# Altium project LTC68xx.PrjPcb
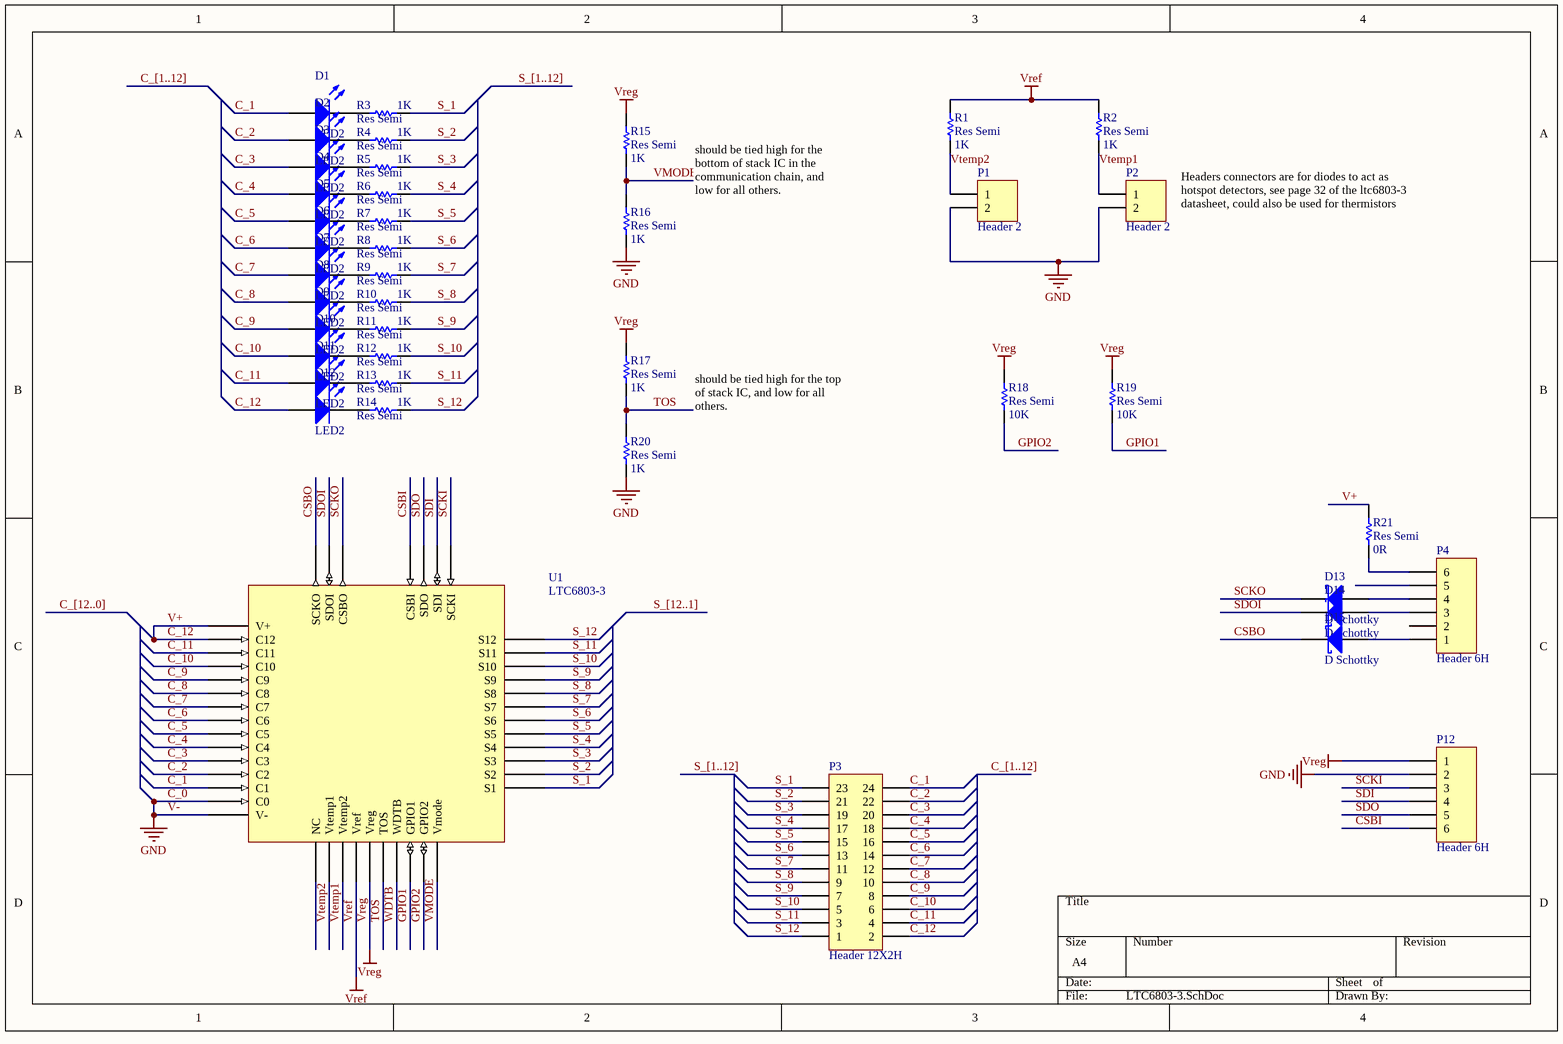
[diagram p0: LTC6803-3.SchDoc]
1 sheet, 42 parts. Net scope: global (net labels, ports and power ports of the same name join across sheets).
Board file: LTC68xx.PcbDoc

## Sheet LTC6803-3.SchDoc
size A4

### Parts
D1  LED2  [6-0805_N]
D2  LED2  [6-0805_N]
D3  LED2  [6-0805_N]
D4  LED2  [6-0805_N]
D5  LED2  [6-0805_N]
D6  LED2  [6-0805_N]
D7  LED2  [6-0805_N]
D8  LED2  [6-0805_N]
D9  LED2  [6-0805_N]
D10  LED2  [6-0805_N]
D11  LED2  [6-0805_N]
D12  LED2  [6-0805_N]
D13  D Schottky  [SMB]
D14  D Schottky  [SMB]
D15  D Schottky  [SMB]
P1  Header 2  [HDR1X2]
P2  Header 2  [HDR1X2]
P3  Header 12X2H  [HDR2X12H]
P4  Header 6H  [HDR1X6H]
P12  Header 6H  [HDR1X6H]
R1  Res Semi  value 1K  [6-0805_L]
R2  Res Semi  value 1K  [6-0805_L]
R3  Res Semi  value 1K  [6-0805_L]
R4  Res Semi  value 1K  [6-0805_L]
R5  Res Semi  value 1K  [6-0805_L]
R6  Res Semi  value 1K  [6-0805_L]
R7  Res Semi  value 1K  [6-0805_L]
R8  Res Semi  value 1K  [6-0805_L]
R9  Res Semi  value 1K  [6-0805_L]
R10  Res Semi  value 1K  [6-0805_L]
R11  Res Semi  value 1K  [6-0805_L]
R12  Res Semi  value 1K  [6-0805_L]
R13  Res Semi  value 1K  [6-0805_L]
R14  Res Semi  value 1K  [6-0805_L]
R15  Res Semi  value 1K  [6-0805_L]
R16  Res Semi  value 1K  [6-0805_L]
R17  Res Semi  value 1K  [6-0805_L]
R18  Res Semi  value 10K  [6-0805_L]
R19  Res Semi  value 10K  [6-0805_L]
R20  Res Semi  value 1K  [6-0805_L]
R21  Res Semi  value 0R  [6-0805_L]
U1  LTC6803-3  [SOP44]

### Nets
C_0: P1.2 P2.2 P12.2 R16.1 R20.1 U1.29(C0) U1.30(V-)  [also labelled GND, V-]
Vref: R1.2 R2.2 U1.34(Vref)
Vreg: P12.1 R15.2 R17.2 R18.2 R19.2 U1.35(Vreg)
C_1: D1.1(A) P3.24 U1.27(C1)
C_2: D2.1(A) P3.22 U1.25(C2)
C_3: D3.1(A) P3.20 U1.23(C3)
C_4: D4.1(A) P3.18 U1.21(C4)
C_5: D5.1(A) P3.16 U1.19(C5)
C_6: D6.1(A) P3.14 U1.17(C6)
C_7: D7.1(A) P3.12 U1.15(C7)
C_8: D8.1(A) P3.10 U1.13(C8)
C_9: D9.1(A) P3.8 U1.11(C9)
C_10: D10.1(A) P3.6 U1.9(C10)
C_11: D11.1(A) P3.4 U1.7(C11)
C_12: D12.1(A) P3.2 R21.2 U1.4(V+) U1.5(C12)  [also labelled V+]
CSBI: P12.6 U1.44(CSBI)
CSBO: D15.2(K) U1.3(SCKO)
GPIO1: R19.1 U1.38(GPIO1)
GPIO2: R18.1 U1.39(GPIO2)
S_1: P3.23 R3.2 U1.28(S1)
S_2: P3.21 R4.2 U1.26(S2)
S_3: P3.19 R5.2 U1.24(S3)
S_4: P3.17 R6.2 U1.22(S4)
S_5: P3.15 R7.2 U1.20(S5)
S_6: P3.13 R8.2 U1.18(S6)
S_7: P3.11 R9.2 U1.16(S7)
S_8: P3.9 R10.2 U1.14(S8)
S_9: P3.7 R11.2 U1.12(S9)
S_10: P3.5 R12.2 U1.10(S10)
S_11: P3.3 R13.2 U1.8(S11)
S_12: P3.1 R14.2 U1.6(S12)
SCKI: P12.3 U1.41(SCKI)
SCKO: D13.2(K) U1.1(CSBO)
SDI: P12.4 U1.42(SDI)
SDO: P12.5 U1.43(SDO)
SDOI: D14.2(K) U1.2(SDOI)
TOS: R17.1 R20.2 U1.36(TOS)
VMODE: R15.1 R16.2 U1.40(Vmode)
Vtemp1: P2.1 R2.1 U1.33(Vtemp2)
Vtemp2: P1.1 R1.1 U1.32(Vtemp1)
WDTB: U1.37(WDTB)
NetD1_2: D1.2(K) R3.1
NetD2_2: D2.2(K) R4.1
NetD3_2: D3.2(K) R5.1
NetD4_2: D4.2(K) R6.1
NetD5_2: D5.2(K) R7.1
NetD6_2: D6.2(K) R8.1
NetD7_2: D7.2(K) R9.1
NetD8_2: D8.2(K) R10.1
NetD9_2: D9.2(K) R11.1
NetD10_2: D10.2(K) R12.1
NetD11_2: D11.2(K) R13.1
NetD12_2: D12.2(K) R14.1
NetD13_1: D13.1(A) P4.4
NetD14_1: D14.1(A) P4.3
NetD15_1: D15.1(A) P4.1
NetP4_6: P4.6 R21.1

Not connected (* = marked no-connect by the designer): P4 2 5; U1 31(NC)

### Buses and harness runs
bus C_[1..12]
bus C_[12..0]
bus S_[1..12]
bus S_[12..1]

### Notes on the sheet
- should be tied high for the bottom of stack IC in the communication chain, and low for all others.
- Headers connectors are for diodes to act as hotspot detectors, see page 32 of the ltc6803-3 datasheet, could also be used for thermistors
- should be tied high for the top of stack IC, and low for all others.

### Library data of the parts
D1-D12 = LED2: Typical RED, GREEN, YELLOW, AMBER GaAs LED
D13-D15 = D Schottky: Schottky Diode
P1 P2 = Header 2: Header, 2-Pin
P3 = Header 12X2H: Header, 12-Pin, Dual row, Right Angle
P4 P12 = Header 6H: Header, 6-Pin, Right Angle
R1-R21 = Res Semi: Semiconductor Resistor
